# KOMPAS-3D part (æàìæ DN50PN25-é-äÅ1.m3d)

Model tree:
1. Объединить компоненты:1  (labels: СЕНС DN50PN25-В-ДП1)

Referenced files in D:\Савин\!СЕНСОР\3D для заказчика\!Новый перечень\СЕНС\5. СЕНС-В-ДП\DN50\: СЕНС DN50PN25-В-ДП1.a3d
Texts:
  СЕНС DN50PN25-В-ДП1
  ООО НПП Сенсор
